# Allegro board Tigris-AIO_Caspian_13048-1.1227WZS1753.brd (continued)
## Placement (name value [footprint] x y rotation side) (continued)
R299  243R2F-2-GP  [R402H16]  45.59 85.7 90 top
R300  -  [0R0402-PAD]  155.88 84.85 270 top
R302  5K11R2F-L1-GP  [R402H16]  78.74 71.87 180 bottom
R303  8K45R2F-2-GP  [R402H16]  95.5 90.79 90 top
R304  1KR2F-3-GP  [R402H16]  79.76 71.87 180 bottom
R305  20KR2F-L-GP  [R402H16]  149.68 93.86 0 top
R306  20KR2F-L-GP  [R402H16]  153.82 95.13 90 top
R307  1KR2J-1-GP  [R402H16]  152.14 84.6 90 top
R308  2K1R2F-GP  [R402H16]  43.97 84.14 0 top
R309  2K1R2F-GP  [R402H16]  46 84.14 180 top
R311  0R5J-5-GP  [R805H24]  13.23 83.91 270 top
R312  10MR3F-GP  [R603H22]  155.42 86.78 0 top
R313  10KR2J-3-GP  [R402H16]  152.15 83.55 90 top
R314  4K7R2J-2-GP  [R402H16]  154.91 90.28 0 top
R316  7K5R2F-1DL-GP  [R402H16]  122.01 83.16 0 top
R318  1KR2J-1-GP  [R402H16]  125.25 101.05 0 bottom
R320  243R2F-2-GP  [R402H16]  45.59 82.52 90 top
R321  1KR2J-1-GP  [R402H16]  152.15 82.41 270 top
R322  1KR2J-1-GP  [R402H16]  125.45 98.46 0 bottom
R323  2K2R2J-2-GP  [R402H16]  177.04 82.41 270 top
R324  2K2R2J-2-GP  [R402H16]  179.07 82.41 270 top
R325  0R5J-5-GP  [R805H24]  37.8 82.33 270 top
R329  47KR2F-GP  [R402H16]  112.39 81.64 270 top
R331  10KR2F-2-GP  [R402H16]  181.61 81.9 180 top
R332  5K1R2F-2-GP  [R402H16]  182.88 81.9 180 top
R333  20KR2F-L-GP  [R402H16]  184.15 81.9 0 top
R334  1KR2J-1-GP  [R402H16]  157.48 81.81 270 top
R335  1KR2J-1-GP  [R402H16]  149.61 81.26 90 top
R336  2K2R2J-2-GP  [R402H16]  177.04 81.26 270 top
R337  10KR2J-3-GP  [R402H16]  179.07 81.26 90 top
R340  10KR2J-3-GP  [R402H16]  120.4 80.88 270 top
R341  40D2R2F-GP  [R402H16]  45.59 80.75 270 top
R342  1KR2J-1-GP  [R402H16]  151.51 80.66 180 top
R343  1KR2J-1-GP  [R402H16]  152.52 80.66 180 top
R344  0R5J-5-GP  [R805H24]  37.8 80.4 270 top
R345  47KR2F-GP  [R402H16]  110.74 80.37 0 top
R346  10KR2J-3-GP  [R402H16]  155.45 80.46 270 top
R347  33R2J-2-GP  [R402H16]  159.1 80.16 270 top
R348  10KR2J-3-GP  [R402H16]  33.32 80.1 90 top
R349  10KR2J-3-GP  [R402H16]  120.4 79.74 270 top
R350  10KR2J-3-GP  [R402H16]  162.94 79.1 90 top
R351  10R2F-L-GP  [R402H14]  177.42 79.61 180 top
R352  40D2R2F-GP  [R402H16]  45.59 79.6 270 top
R353  33R2J-2-GP  [R402H16]  159.1 79.11 270 top
R354  0R2J-2-GP  [R402H16]  108.71 78.85 90 top
R355  10KR2J-3-GP  [R402H16]  162.94 77.96 90 top
R356  1KR2J-1-GP  [R402H16]  110.74 78.34 0 top
R357  10KR2J-3-GP  [R402H16]  159.1 78.07 90 top
R358  -  [0R0805-PAD]  31.8 77.78 0 top
R359  2D2R5J-1-GP  [R805H24]  33.76 77.78 0 top
R360  0R0402-PAD-2-GP  [0R0402-PAD-1]  108.71 77.71 270 top
R361  10KR2J-3-GP  [R402H16]  153.16 77.45 270 top
R362  7K15R2F-L-GP  [R402H16]  30.28 77.17 180 top
R366  33R2J-2-GP  [R402H16]  159.1 77.03 270 top
R367  10KR2J-3-GP  [R402H16]  162.94 76.27 90 top
R368  0R0603-PAD-2-GP-U  [0R0603-PAD-1-U]  190.17 77.17 0 bottom
R371  2D2R3J-2-GP  [R603H22]  37.29 76.72 90 top
R372  33R2J-2-GP  [R402H16]  159.1 75.99 270 top
R373  10KR2J-3-GP  [R402H16]  162.94 75.23 90 top
R374  10KR2J-3-GP  [R402H16]  155.45 75.68 270 top
R375  -  [0R0402-PAD]  192.66 74.3 180 top
R377  33R2J-2-GP  [R402H16]  159.1 74.95 270 top
R378  10KR2J-3-GP  [R402H16]  162.94 74.19 90 top
R379  33R2J-2-GP  [R402H16]  155.45 74.53 270 top
R380  100KR2F-L1-GP  [R402H16]  193.17 72.81 90 top
R381  1KR2J-1-GP  [R402H16]  162.93 73.11 270 top
R382  7K5R2F-1DL-GP  [R402H16]  119.51 73.64 0 top
R383  1KR2J-1-GP  [R402H16]  155.45 73.39 270 top
R384  10KR2J-3-GP  [R402H16]  38.61 72.88 270 top
R385  10KR2J-3-GP  [R402H16]  159.13 72.75 270 top
R386  1MR3F-GP  [R603H22]  198.63 73.52 0 top
R387  0R0402-PAD-2-GP  [0R0402-PAD-1]  162.94 71.99 270 top
R388  8K45R2F-2-GP  [R402H16]  92.48 90 270 bottom
R389  33R2J-2-GP  [R402H16]  155.44 72.31 270 top
R391  2K2R2J-2-GP  [R402H16]  114.3 81.64 90 top
R392  33R2J-2-GP  [R402H16]  155.44 71.27 270 top
R394  2KR2F-3-GP  [R402H16]  90.07 89.62 180 bottom
R395  33R2J-2-GP  [R402H16]  159.13 70.5 270 top
R396  10KR2J-L-GP  [R402H15]  76.45 71.1 180 bottom
R397  10KR2J-L-GP  [R402H15]  77.62 71.08 180 bottom
R398  10KR2J-L-GP  [R402H15]  76.45 71.1 0 top
R399  10KR2J-L-GP  [R402H15]  75.31 71.87 0 top
R400  158R2F-GP  [R402H16]  38.61 69.96 90 top
R403  100R2F-L1-GP-U  [R402H14]  87.37 69.82 0 top
R406  0R3J-0-U-GP  [R603H22]  26.34 69.38 270 top
R407  1KR2J-1-GP  [R402H16]  159.13 69.36 270 top
R408  22D6R2F-L1-GP  [R402H16]  153.54 69.33 0 top
R410  2K21R3F-L-GP  [R603H22]  38.48 68.82 270 top
R411  7K5R2F-1DL-GP  [R402H16]  120.65 68.73 0 top
R412  158R2F-GP  [R402H16]  36.2 68.69 90 top
R413  100KR2J-1-GP  [R402H16]  82.75 68.54 0 top
R415  1KR2J-1-GP  [R402H16]  159.13 68.22 270 top
R417  3K3R2F-2-GP  [R402H16]  32.29 67.82 0 top
R418  2K21R3F-L-GP  [R603H22]  36.96 67.55 90 top
R419  1KR2J-1-GP  [R402H16]  153.54 67.33 0 top
R420  75R2F-2-GP  [R402H16]  38.86 67.17 0 top
R421  0R0402-PAD-2-GP  [0R0402-PAD-1]  159.13 67.07 270 top
R422  47KR2F-GP  [R402H16]  51.69 66.91 0 top
R423  100KR2J-1-GP  [R402H16]  52.83 66.91 180 top
R424  1KR2J-1-GP  [R402H16]  148.08 32.75 90 top
R425  1KR2J-1-GP  [R402H16]  141.48 32.62 0 top
R426  10KR2J-3-GP  [R402H16]  55.17 66.45 90 top
R427  10KR2J-3-GP  [R402H16]  111.85 65.34 270 top
R428  100KR2J-1-GP  [R402H16]  51.49 64.79 0 top
R429  0R0402-PAD-2-GP  [0R0402-PAD-1]  161.87 63.96 0 top
R430  4K7R2J-2-GP  [R402H16]  33.78 64.63 180 top
R431  0R5J-5-GP  [R805H24]  36.17 63.79 270 top
R432  10KR2J-3-GP  [R402H16]  149.86 61.71 0 top
R433  100KR2J-1-GP  [R402H16]  51.49 62.89 0 top
R434  22R2J-2-GP  [R402H16]  154.58 59.04 180 top
R435  33R2J-2-GP  [R402H16]  161.87 61.8 0 top
R436  33R2J-2-GP  [R402H16]  163.01 61.8 0 top
R437  10KR2F-2-GP  [R402H16]  86.87 61.71 270 top
R438  0R0402-PAD-2-GP  [0R0402-PAD-1]  156.46 61.71 180 top
R439  22R2J-2-GP  [R402H16]  151.38 59.04 0 top
R440  1KR2J-1-GP  [R402H16]  46.05 60.77 180 top
R441  1KR2J-1-GP  [R402H16]  41.33 59.93 0 top
R442  150R2F-1-GP  [R402H16]  137.41 59.4 0 top
R443  150R2F-1-GP  [R402H16]  138.45 59.4 0 top
R444  150R2F-1-GP  [R402H16]  139.49 59.4 0 top
R445  10KR2J-3-GP  [R402H16]  46.38 59.04 270 top
R446  22R2J-2-GP  [R402H16]  152.5 59.04 180 top
R447  22R2J-2-GP  [R402H16]  153.51 59.04 180 top
R448  1KR2J-1-GP  [R402H16]  46.41 58 90 top
R449  0R0402-PAD-2-GP  [0R0402-PAD-1]  41.33 57.9 0 top
R450  10KR2J-3-GP  [R402H16]  58.88 55.97 180 top
R451  0R0402-PAD-2-GP  [0R0402-PAD-1]  60.05 55.91 0 top
R452  330KR2F-L-GP  [R402H16]  61.19 55.91 180 top
R453  -  [0R0402-PAD]  43.52 55.89 0 top
R454  33R2J-2-GP  [R402H16]  45.43 55.89 0 top
R455  10KR2J-3-GP  [R402H16]  46.62 55.88 180 top
R456  0R0402-PAD-2-GP  [0R0402-PAD-1]  42.42 55.86 0 top
R457  33R2J-2-GP  [R402H16]  50.67 55.86 0 top
R458  10KR2J-3-GP  [R402H16]  52.87 55.83 180 top
R459  33R2J-2-GP  [R402H16]  49.63 55.81 0 top
R460  10KR2J-3-GP  [R402H16]  51.82 55.81 0 top
R461  10KR2J-3-GP  [R402H16]  53.9 55.81 180 top
R462  -  [0R0805-PAD]  125.86 55.74 0 top
R463  10KR2J-3-GP  [R402H16]  48.13 55.46 270 top
R464  10KR2F-2-GP  [R402H16]  129.19 54.73 90 top
R465  0R2J-2-GP  [R402H16]  136.02 54.69 90 top
R466  20KR2J-L2-GP  [R402H16]  147.07 54.72 270 top
R467  1MR3F-GP  [R603H22]  118.41 54.17 90 top
R468  1KR2J-1-GP  [R402H16]  139.19 54.12 90 top
R469  10KR2J-3-GP  [R402H16]  145.16 54.72 90 top
R470  22KR2J-GP  [R402H16]  141.1 55.36 270 top
R471  10KR2J-3-GP  [R402H16]  149.35 45.07 0 top
R472  0R2J-2-GP  [R402H16]  148.34 45.07 0 top
R473  43R2J-GP  [R402H16]  65.02 53.32 270 top
R474  4K7R2J-2-GP  [R402H16]  150.88 43.29 180 top
R475  0R0402-PAD-2-GP  [0R0402-PAD-1]  142.62 46.08 270 top
R476  4K7R2J-2-GP  [R402H16]  139.83 44.18 90 top
R477  8K87R2F-2-GP  [R402H16]  128.11 53.19 270 top
R478  20KR2J-L2-GP  [R402H16]  42.09 53.17 90 top
R479  10KR2F-2-GP  [R402H16]  139.19 52.98 270 top
R480  4K7R2J-2-GP  [R402H16]  65.02 52.18 90 top
R481  0R0402-PAD-2-GP  [0R0402-PAD-1]  65.02 51.04 270 top
R482  4K7R2J-2-GP  [R402H16]  65.02 49.89 90 top
R483  4K7R2J-2-GP  [R402H16]  143.64 50.91 0 top
R484  1KR2J-1-GP  [R402H16]  144.53 49.39 90 top
R485  10KR2J-3-GP  [R402H16]  146.43 49.39 90 top
R486  0R0402-PAD-2-GP  [0R0402-PAD-1]  149.99 49.51 90 top
R487  20KR2J-L2-GP  [R402H16]  152.02 50.4 90 top
R488  0R0402-PAD-2-GP  [0R0402-PAD-1]  103.61 49.13 180 top
R489  20KR2J-L2-GP  [R402H16]  103.9 51.01 270 top
R490  8K2R2F-1-GP  [R402H16]  104.7 49.11 0 top
R491  4K7R2J-2-GP  [R402H16]  105.76 49.12 180 top
R492  4K7R2J-2-GP  [R402H16]  42.04 51.04 270 top
R493  4K7R2J-2-GP  [R402H16]  65.02 48.75 90 top
R494  1KR2J-1-GP  [R402H16]  38.35 48.24 270 top
R495  4K7R2J-2-GP  [R402H16]  42.04 49.77 270 top
R496  0R0402-PAD-2-GP  [0R0402-PAD-1]  65.02 47.61 270 top
R497  15KR2F-GP  [R402H16]  36.7 47.74 0 top
R498  8K2R2J-3-GP  [R402H16]  38.35 47.1 270 top
R499  0R3J-0-U-GP  [R603H22]  159.87 43.93 270 top
R500  2K2R2J-2-GP  [R402H16]  164.62 43.32 270 top
R501  4K7R2J-2-GP  [R402H16]  42.19 46.85 90 top
R503  10KR5F-2-GP  [R805H24]  6.86 46.21 270 top
R504  10KR2J-3-GP  [R402H16]  9.27 46.21 0 top
R505  4K7R2J-2-GP  [R402H16]  42.19 45.7 270 top
R506  0R3J-0-U-GP  [R603H22]  165.23 41.77 90 top
R507  3KR2J-2-GP  [R402H16]  17.73 45.58 90 top
R508  4K7R2J-2-GP  [R402H16]  125.13 45.2 270 top
R509  10KR2J-3-GP  [R402H16]  127.29 45.2 90 top
R511  0R3J-0-U-GP  [R603H22]  154.64 41.94 90 top
R512  -  [0R0805-PAD]  131.57 44.69 90 top
R513  4K7R2J-2-GP  [R402H16]  42.19 44.43 90 top
R514  20KR2F-L-GP  [R402H16]  104.78 44.43 90 top
R515  5K6R2F-2-GP  [R402H16]  160.78 40.5 180 top
R516  100KR2J-1-GP  [R402H16]  161.93 40.5 0 top
R517  10KR2F-2-GP  [R402H16]  163.07 40.5 0 top
R518  0R2J-2-GP  [R402H16]  65.02 44.18 90 top
R519  0R2J-2-GP  [R402H16]  101.22 43.93 180 top
R520  100KR2J-1-GP  [R402H16]  152.53 39.99 180 top
R521  4K7R2J-2-GP  [R402H16]  42.19 43.29 270 top
R522  0R3J-0-U-GP  [R603H22]  30.53 42.78 180 top
R523  -  [0R0402-PAD]  99.95 42.99 180 top
R524  330R3J-L-GP  [R603H22]  23.9 42.78 180 top
R526  0R3J-0-U-GP  [R603H22]  165.2 38.03 90 top
R527  10KR2J-3-GP  [R402H16]  41.81 40.9 90 top
R528  100KR2J-1-GP  [R402H16]  106.93 40.75 270 top
R529  10KR2J-3-GP  [R402H16]  108.84 40.75 270 top
R530  47KR2F-GP  [R402H16]  110.87 40.75 270 top
R531  100KR2J-1-GP  [R402H16]  112.83 40.73 90 top
R533  100R2F-L1-GP-U  [R402H14]  116.55 39.98 180 top
R534  2K2R2J-2-GP  [R402H16]  117.7 39.98 180 top
R535  10KR2J-3-GP  [R402H16]  42.01 39.58 270 top
R536  1KR2J-1-GP  [R402H16]  114.47 39.48 0 top
R537  10KR2J-3-GP  [R402H16]  16.76 39.23 90 top
R538  10R3J-3-GP  [R603H22]  154.05 34.65 180 top
R539  147KR2F-GP  [R402H16]  100.58 38.34 90 top
R540  3KR2J-2-GP  [R402H16]  16.76 38.08 270 top
R541  0R0402-PAD-2-GP  [0R0402-PAD-1]  164.72 33.77 180 top
R542  100KR2J-1-GP  [R402H16]  114.43 37.51 0 top
R543  10KR2J-3-GP  [R402H16]  41.91 37.32 90 top
R544  1KR2J-1-GP  [R402H16]  35.76 37.22 90 top
R545  10KR2J-3-GP  [R402H16]  40.39 36.56 180 top
R546  1MR3F-GP  [R603H22]  23.11 36.86 180 top
R547  10KR2J-3-GP  [R402H16]  41.91 36.18 90 top
R548  2KR2F-3-GP  [R402H16]  35.76 36.15 90 top
R549  33R2J-2-GP  [R402H16]  16.74 35.95 90 top
R550  200KR2F-L-GP  [R402H16]  102.47 35.35 180 top
R551  0R2J-2-GP  [R402H16]  43.69 36.69 0 top
R552  100KR2J-1-GP  [R402H16]  135.61 34.49 90 top
R553  100KR2J-1-GP  [R402H16]  137.57 34.45 90 top
R554  15KR2F-GP  [R402H16]  116.51 34.32 270 top
R555  2K49R2F-GP  [R402H16]  24.13 34.27 180 top
R556  10KR2J-3-GP  [R402H16]  118.24 33.89 180 top
R557  1KR2J-1-GP  [R402H16]  113.87 33.84 180 top
R558  1KR2J-1-GP  [R402H16]  114.91 33.84 180 top
R559  0R2J-2-GP  [R402H16]  35.76 33.08 90 top
R560  1KR2J-1-GP  [R402H16]  61.47 32.62 180 top
R561  10KR2J-3-GP  [R402H16]  62.48 32.62 0 top
R562  0R2J-2-GP  [R402H16]  60.32 32.58 180 top
R563  0R0402-PAD-2-GP  [0R0402-PAD-1]  58.14 32.55 0 top
R564  0R2J-2-GP  [R402H16]  59.16 32.55 0 top
R565  30KR2F-GP  [R402H16]  52.12 32.5 180 top
R566  30KR2F-GP  [R402H16]  53.19 32.5 180 top
R567  30KR2F-GP  [R402H16]  54.2 32.5 180 top
R568  160R2F-GP  [R402H16]  47.5 32.22 0 top
R569  4K7R2J-2-GP  [R402H16]  16.76 32.11 270 top
R571  33R2J-2-GP  [R402H16]  16.76 31.1 270 top
R572  0R0402-PAD-2-GP  [0R0402-PAD-1]  43.69 30.97 0 top
R573  4K7R2J-2-GP  [R402H16]  42.52 30.95 0 top
R574  30KR2F-GP  [R402H16]  47.5 30.31 180 top
R575  4K7R2J-2-GP  [R402H16]  112.04 30.08 0 top
R576  47KR2F-GP  [R402H16]  132.18 29.88 180 top
R577  10KR2J-3-GP  [R402H16]  133.48 29.88 180 top
R578  0R2J-2-GP  [R402H16]  160.53 22.08 0 top
R579  10KR2J-3-GP  [R402H16]  10.16 18.53 180 top
R583  2K2R2J-2-GP  [R402H16]  65.28 28.3 0 top
R584  47KR2F-GP  [R402H16]  132.08 28.15 270 top
R586  3D3R3F-GP  [R603H22]  147.57 21.07 0 top
R587  3D3R3F-GP  [R603H22]  147.57 23.99 180 top
R588  3D3R3F-GP  [R603H22]  147.57 26.91 0 top
R589  3D3R3F-GP  [R603H22]  147.57 29.83 180 top
R590  0R2J-2-GP  [R402H16]  159.51 22.08 0 top
R591  15KR2F-GP  [R402H16]  104.01 27.14 0 top
R592  10KR2J-3-GP  [R402H16]  105.16 27.14 180 top
R593  10KR2J-3-GP  [R402H16]  132.08 27.03 270 top
R595  330R3J-L-GP  [R603H22]  19.68 25.99 0 top
R596  330R3J-L-GP  [R603H22]  20.88 25.99 0 top
R597  100KR2J-1-GP  [R402H16]  139.19 32.62 0 top
R599  2K2R2J-2-GP  [R402H16]  59.31 24.75 180 top
R600  1MR2J-1-GP  [R402H16]  65.28 25.89 0 top
R601  100KR2J-1-GP  [R402H16]  134.08 24.64 0 top
R602  0R3J-0-U-GP  [R603H22]  14.48 24.85 90 bottom
R605  150R2F-1-GP  [R402H16]  32.44 21.93 0 top
R606  150R2F-1-GP  [R402H16]  39.09 21.88 0 top
R609  150R2F-1-GP  [R402H16]  37.9 22.18 0 top
R614  20KR2J-L2-GP  [R402H16]  62.91 20.18 270 top
R623  2K2R2J-2-GP  [R402H16]  33.1 11.72 90 top
R624  47R2J-2-GP  [R402H16]  70.38 7.82 180 top
R625  47R2J-2-GP  [R402H16]  71.52 7.82 180 top
R626  2K2R2J-2-GP  [R402H16]  32.54 6.87 270 top
R629  110R2F-GP  [R402H16]  19.3 245.96 0 bottom
R630  0R0402-PAD-2-GP  [0R0402-PAD-1]  17.07 245.96 180 bottom
R631  2D2R5J-1-GP  [R805H24]  14.73 245.91 90 bottom
R632  10KR2F-2-GP  [R402H16]  4.62 244.76 180 bottom
R633  1KR2J-1-GP  [R402H16]  11.07 245.5 180 bottom
R634  0R0402-PAD-2-GP  [0R0402-PAD-1]  9.91 245.53 0 bottom
R635  56K2R2F-2-GP  [R402H16]  25.2 245.25 90 bottom
R636  0R0402-PAD-2-GP  [0R0402-PAD-1]  58.42 245.22 180 bottom
R637  0R0402-PAD-2-GP  [0R0402-PAD-1]  57.28 245.22 180 bottom
R638  1KR2J-1-GP  [R402H16]  56.01 245.22 180 bottom
R639  51R2F-2-GP  [R402H16]  53.72 245.22 180 bottom
R640  825R2F-GP  [R402H16]  52.45 245.22 0 bottom
R641  100R2F-L1-GP-U  [R402H14]  51.31 245.22 0 bottom
R642  249R2F-GP  [R402H16]  50.04 245.22 180 bottom
R643  51R2J-2-GP  [R402H16]  48.77 245.22 180 bottom
R644  51R2J-2-GP  [R402H16]  47.5 245.22 180 bottom
R645  51R2J-2-GP  [R402H16]  46.23 245.22 180 bottom
R646  1KR2J-1-GP  [R402H16]  44.96 245.22 0 bottom
R647  1KR2J-1-GP  [R402H16]  22.38 244.48 180 bottom
R648  54D9R2F-L1-GP  [R402H16]  20.35 244.05 180 bottom
R649  90D9R2F-1-GP  [R402H16]  19.3 244.05 180 bottom
R650  0R0402-PAD-2-GP  [0R0402-PAD-1]  25.2 244.1 270 bottom
R651  0R0402-PAD-2-GP  [0R0402-PAD-1]  11.58 243.82 270 bottom
R652  100R2F-L1-GP-U  [R402H14]  9.68 243.82 90 bottom
R653  100R2F-L1-GP-U  [R402H14]  9.42 242.58 90 bottom
R654  100KR2J-1-GP  [R402H16]  105.16 242.55 180 bottom
R655  20K5R2F-GP  [R402H16]  22.89 242.45 270 bottom
R656  1K2R2F-1-GP  [R402H16]  11.56 241.54 90 bottom
R657  69K8R2F-GP  [R402H16]  22.89 241.31 270 bottom
R658  10KR2F-2-GP  [R402H16]  5.36 240.22 90 bottom
R659  0R0402-PAD-2-GP  [0R0402-PAD-1]  111.76 233.92 180 bottom
R660  100KR2J-1-GP  [R402H16]  105.16 240.52 0 bottom
R661  47D5R2F-1-GP  [R402H16]  11.58 240.29 270 bottom
R662  59KR2F-GP  [R402H16]  22.89 240.17 270 bottom
R663  10KR2F-2-GP  [R402H16]  4.93 238.74 0 bottom
R664  0R0402-PAD-2-GP  [0R0402-PAD-1]  112.78 233.92 180 bottom
R665  1KR2F-3-GP  [R402H16]  11.58 239.15 270 bottom
R666  68KR2F-GP  [R402H16]  22.89 239.02 270 bottom
R667  10KR2F-2-GP  [R402H16]  5.97 238.72 180 bottom
R668  560KR2F-GP  [R402H16]  8.92 238.52 0 bottom
R669  0R0402-PAD-2-GP  [0R0402-PAD-1]  114.68 234.68 270 bottom
R670  4K99R2F-L-GP  [R402H16]  10.95 237.63 0 bottom
R671  6K8R2F-2-GP  [R402H16]  24.92 237.12 270 bottom
R672  0R0402-PAD-2-GP  [0R0402-PAD-1]  114.68 235.7 270 bottom
R673  0R0402-PAD-2-GP  [0R0402-PAD-1]  9.4 236.8 270 bottom
R674  100KR2F-L1-GP  [R402H16]  22.38 236.61 0 bottom
R675  18KR2F-GP  [R402H16]  14.45 236.15 180 bottom
R676  0R0402-PAD-2-GP  [0R0402-PAD-1]  114.17 231.94 90 bottom
R677  1KR2J-1-GP  [R402H16]  10.95 235.47 0 bottom
R678  100KR2F-L1-GP  [R402H16]  21.87 235.09 270 bottom
R679  100KR2F-L1-GP  [R402H16]  19.84 235.09 270 bottom
R680  0R0402-PAD-2-GP  [0R0402-PAD-1]  108.2 221.6 180 bottom
R681  10R2F-L-GP  [R402H14]  18.29 234.68 0 bottom
R682  10R2F-L-GP  [R402H14]  23.5 234.55 180 bottom
R683  75KR2F-GP  [R402H16]  14.5 234.2 180 bottom
R684  10R2F-L-GP  [R402H14]  26.16 234.04 90 bottom
R685  0R0402-PAD-2-GP  [0R0402-PAD-1]  109.22 221.6 180 bottom
R686  174KR2F-GP  [R402H16]  16 233.66 90 bottom
R687  118KR3F-GP  [R603H22]  15.57 232.44 90 bottom
R688  31K6R2F-GP  [R402H16]  12.06 232.39 180 bottom
R689  10KR2F-2-GP  [R402H16]  9.78 232.39 180 bottom
R690  6K8R2F-2-GP  [R402H16]  22.38 232.17 180 bottom
R691  6K8R2F-2-GP  [R402H16]  20.35 232.17 180 bottom
R692  118KR3F-GP  [R603H22]  23.55 230.77 180 bottom
R693  118KR3F-GP  [R603H22]  20.29 229.73 180 bottom
R694  2D2R5J-1-GP  [R805H24]  14.54 229.29 270 bottom
R695  1KR2F-3-GP  [R402H16]  54.41 228.28 180 bottom
R696  1KR2J-1-GP  [R402H16]  53.39 228.28 0 bottom
R697  0R0402-PAD-2-GP  [0R0402-PAD-1]  52.25 228.28 0 bottom
R698  0R0402-PAD-2-GP  [0R0402-PAD-1]  51.1 228.28 0 bottom
R699  51R2J-2-GP  [R402H16]  49.07 228.28 0 bottom
R700  100KR2J-1-GP  [R402H16]  111.63 223.12 0 bottom
R701  51R2J-2-GP  [R402H16]  15.17 226.36 270 bottom
R702  100KR2J-1-GP  [R402H16]  112.01 221.6 90 bottom
R703  0R3J-0-U-GP  [R603H22]  167.39 223.25 270 bottom
R704  2D2R5J-1-GP  [R805H24]  19.11 222.93 270 bottom
R705  0R3J-0-U-GP  [R603H22]  169.42 222.49 0 bottom
R706  330R3J-L-GP  [R603H22]  116.71 223.38 180 bottom
R707  47KR2F-GP  [R402H16]  112.9 220.58 270 bottom
R708  100KR2J-1-GP  [R402H16]  112.9 219.44 90 bottom
R709  0R6J-3-GP  [R1206H28]  121.41 217.92 270 bottom
R710  -  [0R0805-PAD]  157.99 217.66 90 bottom
R711  -  [0R0805-PAD]  157.99 216.26 90 bottom
R712  -  [0R0805-PAD]  157.99 214.87 90 bottom
R713  100KR2J-1-GP  [R402H16]  126.64 213.6 0 bottom
R714  0R2J-2-GP  [R402H16]  125.6 213.6 0 bottom
R715  0R0402-PAD-2-GP  [0R0402-PAD-1]  124.59 213.6 0 bottom
R717  0R2J-2-GP  [R402H16]  122.56 213.6 180 bottom
R718  1KR2J-1-GP  [R402H16]  81.41 208.52 180 bottom
R719  1KR2J-1-GP  [R402H16]  79.63 208.52 180 bottom
R720  1KR2J-1-GP  [R402H16]  77.72 208.52 180 bottom
R721  1KR2J-1-GP  [R402H16]  76.2 208.52 180 bottom
R722  1KR2J-1-GP  [R402H16]  73.91 208.52 180 bottom
R723  1KR2J-1-GP  [R402H16]  72.01 208.52 180 bottom
R724  4K7R2J-2-GP  [R402H16]  121.41 208.39 180 bottom
R725  4K7R2J-2-GP  [R402H16]  120.4 208.39 180 bottom
R726  4K7R2J-2-GP  [R402H16]  118.87 208.16 270 bottom
R727  4K7R2J-2-GP  [R402H16]  116.97 208.16 90 bottom
R728  49D9R2F-GP  [R402H16]  66.55 207.5 0 bottom
R729  2D2R5J-1-GP  [R805H24]  14.41 206.93 270 bottom
R730  0R0402-PAD-2-GP  [0R0402-PAD-1]  137.92 205.72 90 bottom
R731  1KR2J-1-GP  [R402H16]  81.41 205.72 0 bottom
R732  1KR2J-1-GP  [R402H16]  79.63 205.72 0 bottom
R733  1KR2J-1-GP  [R402H16]  77.72 205.72 0 bottom
R734  1KR2J-1-GP  [R402H16]  76.33 205.72 0 bottom
R735  1KR2J-1-GP  [R402H16]  73.91 205.72 0 bottom
R736  1KR2J-1-GP  [R402H16]  72.01 205.72 0 bottom
R738  10KR2J-3-GP  [R402H16]  135.46 205.29 0 bottom
R739  1KR2J-1-GP  [R402H16]  134.37 203.44 180 bottom
R740  0R0402-PAD-2-GP  [0R0402-PAD-1]  85.45 205.26 0 bottom
R741  0R0402-PAD-2-GP  [0R0402-PAD-1]  84.3 205.26 0 bottom
R742  0R0402-PAD-2-GP  [0R0402-PAD-1]  60.58 205.09 270 bottom
R743  0R0402-PAD-2-GP  [0R0402-PAD-1]  67.69 204.45 180 bottom
R744  0R0402-PAD-2-GP  [0R0402-PAD-1]  66.55 204.45 0 bottom
R745  0R0402-PAD-2-GP  [0R0402-PAD-1]  63.37 204.33 180 bottom
R746  44D2R2F-GP  [R402H16]  62.21 204.32 180 bottom
R748  100KR2J-1-GP  [R402H16]  137.54 204.2 180 bottom
R749  75R2F-2-GP  [R402H16]  60.58 203.95 270 bottom
R750  51R2J-2-GP  [R402H16]  15.11 203.95 270 bottom
R751  1KR2J-1-GP  [R402H16]  81.41 203.69 180 bottom
R752  1KR2J-1-GP  [R402H16]  79.63 203.69 180 bottom
R753  1KR2J-1-GP  [R402H16]  77.72 203.69 180 bottom
R754  1KR2J-1-GP  [R402H16]  74.3 203.69 180 bottom
R755  1KR2J-1-GP  [R402H16]  72.39 203.69 180 bottom
R756  1KR2J-1-GP  [R402H16]  69.98 203.31 180 bottom
R757  1K8R2F-GP  [R402H16]  86.74 203.18 90 bottom
R758  24D9R2F-L-GP  [R402H16]  84.71 203.18 270 bottom
R759  1MR2J-L2-GP  [R402H16]  133.86 201.91 90 bottom
R760  100KR2J-1-GP  [R402H16]  131.95 201.91 90 bottom
R762  100KR2J-1-GP  [R402H16]  133.86 200.9 90 bottom
R763  1MR2J-L2-GP  [R402H16]  131.95 200.9 90 bottom
R764  0R0402-PAD-2-GP  [0R0402-PAD-1]  86.22 201.59 180 bottom
R765  3K3R2J-3-GP  [R402H16]  85.07 201.59 180 bottom
R767  90D9R2F-1-GP  [R402H16]  63.37 201.53 0 bottom
R768  100R2F-L1-GP-U  [R402H14]  62.23 201.48 180 bottom
R769  110R2F-GP  [R402H16]  61.09 201.48 180 bottom
R770  0R0402-PAD-2-GP  [0R0402-PAD-1]  59.95 201.48 180 bottom
R771  0R0402-PAD-2-GP  [0R0402-PAD-1]  69.98 201.41 0 bottom
R772  0R2J-2-GP  [R402H16]  68.83 201.41 180 bottom
R773  0R2J-2-GP  [R402H16]  67.79 201.41 0 bottom
R774  51R2J-2-GP  [R402H16]  66.78 201.41 0 bottom
R775  1KR2J-1-GP  [R402H16]  81.41 201.15 0 bottom
R776  1KR2J-1-GP  [R402H16]  74.3 201.15 0 bottom
R777  1KR2J-1-GP  [R402H16]  72.39 201.08 0 bottom
R779  2D2R5J-1-GP  [R805H24]  19.18 200.26 270 bottom
R783  -  [0R0805-PAD]  159 195.31 180 bottom
R784  -  [0R0805-PAD]  157.61 195.31 180 bottom
R785  -  [0R0805-PAD]  156.21 195.31 180 bottom
R786  -  [0R0805-PAD]  154.81 195.31 180 bottom
R787  -  [0R0805-PAD]  153.42 195.31 180 bottom
R788  -  [0R0805-PAD]  152.02 195.31 180 bottom
R789  -  [0R0805-PAD]  150.62 195.31 180 bottom
R790  -  [0R0805-PAD]  149.22 195.31 180 bottom
R791  2D2R5J-1-GP  [R805H24]  184.02 191.25 0 bottom
R792  2R2F-GP  [R402H16]  158.88 188.83 90 bottom
R793  2R2F-GP  [R402H16]  164.34 188.71 90 bottom
R794  10KR2F-2-GP  [R402H16]  179.83 188.58 0 bottom
R795  24D9R2F-L-GP  [R402H16]  165.86 188.32 180 bottom
R796  24D9R2F-L-GP  [R402H16]  160.53 187.31 0 bottom
R797  0R0402-PAD-2-GP  [0R0402-PAD-1]  158.5 187.31 0 bottom
R798  0R3J-0-U-GP  [R603H22]  13.89 187.4 90 bottom
R799  0R0402-PAD-2-GP  [0R0402-PAD-1]  163.45 186.04 0 bottom
R800  1KR2F-3-GP  [R402H16]  157.99 185.78 90 bottom
R801  1KR2F-3-GP  [R402H16]  159.51 185.28 0 bottom
R802  1KR2F-3-GP  [R402H16]  163.07 184.51 270 bottom
R803  1KR2F-3-GP  [R402H16]  162.43 182.99 0 bottom
R804  8K2R2F-1-GP  [R402H16]  14.3 184.24 270 bottom
R805  20KR2J-L2-GP  [R402H16]  12.27 184.24 90 bottom
R806  4K7R2J-2-GP  [R402H16]  10.79 184.64 180 bottom
R807  0R0402-PAD-2-GP  [0R0402-PAD-1]  14.22 183.12 270 bottom
R808  0R0402-PAD-2-GP  [0R0402-PAD-1]  173.48 180.2 270 bottom
R809  0R0402-PAD-2-GP  [0R0402-PAD-1]  158.75 179.92 90 bottom
R810  100R2F-L1-GP-U  [R402H14]  13.97 181.59 0 bottom
R811  2K2R2J-2-GP  [R402H16]  8.28 182.56 0 bottom
R812  10KR2J-3-GP  [R402H16]  24.9 176.72 90 bottom
R813  0R0805-PAD-2-GP-U  [0R0805-PAD-1-U]  24.46 174.3 0 bottom
R814  0R5J-5-GP  [R805H24]  16.18 158.28 0 bottom
R815  0R5J-5-GP  [R805H24]  14.15 158.28 0 bottom
R816  0R5J-5-GP  [R805H24]  18.21 158.28 0 bottom
R817  100KR2J-1-GP  [R402H16]  185.55 162.42 180 bottom
R818  10KR2J-3-GP  [R402H16]  184.53 162.42 180 bottom
R819  100KR2J-1-GP  [R402H16]  183.39 162.42 180 bottom
R820  100KR2J-1-GP  [R402H16]  181.84 163.31 0 bottom
R821  100KR2J-1-GP  [R402H16]  186.59 162.38 0 bottom
R822  56KR3F-GP  [R603H22]  17.02 148.47 0 bottom
R823  0R2J-2-GP  [R402H16]  79.78 158.47 270 bottom
R824  0R3J-0-U-GP  [R603H22]  82.07 158.22 90 bottom
R825  100KR2J-1-GP  [R402H16]  17.4 146.52 90 bottom
R826  0R2J-2-GP  [R402H16]  83.26 157.05 270 bottom
R827  191R2F-GP  [R402H16]  177.47 156.93 270 bottom
R828  49D9R2F-GP  [R402H16]  75.08 156.64 0 bottom
R829  49D9R2F-GP  [R402H16]  74.04 156.64 0 bottom
R830  24D9R2F-L-GP  [R402H16]  77.19 156.44 180 bottom
R831  24D9R2F-L-GP  [R402H16]  76.15 156.44 180 bottom
R832  0R3J-0-U-GP  [R603H22]  19.05 138.29 270 bottom
R833  0R0402-PAD-2-GP  [0R0402-PAD-1]  186.94 155.18 90 bottom
R834  0R3J-0-U-GP  [R603H22]  19.05 137.12 270 bottom
R835  22R2J-2-GP  [R402H16]  186.94 154.03 270 bottom
R836  0R3J-0-U-GP  [R603H22]  19.05 135.95 270 bottom
R837  22R2J-2-GP  [R402H16]  186.94 152.89 270 bottom
R838  0R0402-PAD-2-GP  [0R0402-PAD-1]  185.55 150.61 180 bottom
R839  22R2J-2-GP  [R402H16]  183.01 151.37 90 bottom
R840  22R2J-2-GP  [R402H16]  181.23 152 180 bottom
R841  22R2J-2-GP  [R402H16]  180.09 152 180 bottom
R842  0R3J-0-U-GP  [R603H22]  19.05 134.78 270 bottom
R843  0R5J-5-GP  [R805H24]  15.75 133.84 180 top
R844  0R5J-5-GP  [R805H24]  17.78 133.84 180 top
R845  0R0402-PAD-2-GP  [0R0402-PAD-1]  159.26 146.67 0 bottom
R846  1KR2F-3-GP  [R402H16]  161.54 146.64 180 bottom
R847  1KR2F-3-GP  [R402H16]  160.4 146.64 0 bottom
R848  10KR2J-3-GP  [R402H16]  163.83 127.49 90 bottom
R849  10KR2J-3-GP  [R402H16]  170 125.41 180 bottom
R850  10KR2J-3-GP  [R402H16]  150.6 124.8 0 bottom
R851  10KR2J-3-GP  [R402H16]  153.7 124.72 0 bottom
R852  10KR2J-3-GP  [R402H16]  163.83 124.57 90 bottom
R853  0R6J-3-GP  [R1206H28]  14.73 123.73 90 bottom
R854  -  [0R0805-PAD]  144.93 115.63 180 bottom
R855  15KR2F-GP  [R402H16]  183.97 115.5 180 bottom
R856  10KR2J-3-GP  [R402H16]  182.83 115.5 0 bottom
R857  1KR2F-3-GP  [R402H16]  136.14 114.54 270 bottom
R858  1KR2F-3-GP  [R402H16]  136.42 113.47 270 bottom
R859  1KR2J-1-GP  [R402H16]  185.78 107.81 270 bottom
R860  2D2R3J-2-GP  [R603H22]  129.67 106.82 180 bottom
R861  105KR2F-1-GP  [R402H16]  159.77 102.09 0 bottom
R862  0R0402-PAD-2-GP  [0R0402-PAD-1]  130.3 100.82 270 bottom
R863  10KR2J-3-GP  [R402H16]  141.97 99.42 90 bottom
R864  200R2F-L-GP  [R402H16]  132.28 99.36 180 bottom
R865  200R2F-L-GP  [R402H16]  131.21 99.36 180 bottom
R866  200R2F-L-GP  [R402H16]  130.07 99.36 180 bottom
R867  1KR2J-1-GP  [R402H16]  129.03 99.35 0 bottom
R868  10KR2J-3-GP  [R402H16]  127.99 99.35 0 bottom
R869  2K2R2J-2-GP  [R402H16]  126.97 99.35 180 bottom
R870  243R2F-2-GP  [R402H16]  45.72 98.65 270 bottom
R871  1KR2J-1-GP  [R402H16]  155.93 83.35 180 top
R872  1KR2J-1-GP  [R402H16]  157.45 82.84 270 top
R873  10KR2J-3-GP  [R402H16]  141.98 98.34 270 bottom
R877  1KR2J-1-GP  [R402H16]  141.55 96.77 180 bottom
R878  1KR2J-1-GP  [R402H16]  143.8 96.76 0 bottom
R879  0R0402-PAD-2-GP  [0R0402-PAD-1]  142.64 96.74 0 bottom
R880  10KR2J-3-GP  [R402H16]  148.59 96.63 0 bottom
R885  2K1R2F-GP  [R402H16]  46.35 96.24 180 bottom
R886  2K1R2F-GP  [R402H16]  45.21 96.24 0 bottom
R887  0R0402-PAD-2-GP  [0R0402-PAD-1]  134.82 96.23 180 bottom
R888  10KR2J-3-GP  [R402H16]  133.75 96.23 180 bottom
R889  100R2F-L1-GP-U  [R402H14]  131.95 96 180 bottom
R890  100R2F-L1-GP-U  [R402H14]  130.81 96 180 bottom
R891  100R2F-L1-GP-U  [R402H14]  129.67 96 180 bottom
R892  1KR2J-1-GP  [R402H16]  128.52 96 180 bottom
R893  1KR2J-1-GP  [R402H16]  124.96 95.78 90 bottom
R895  10KR2J-3-GP  [R402H16]  126.49 94.6 0 bottom
R896  33KR2J-3-GP  [R402H16]  184.25 95.51 180 bottom
R897  0R2J-2-GP  [R402H16]  178.31 95.36 0 bottom
R898  10KR2J-3-GP  [R402H16]  124.96 94.76 270 bottom
R899  243R2F-2-GP  [R402H16]  45.84 94.72 270 bottom
R902  0R0603-PAD-2-GP-U  [0R0603-PAD-1-U]  178.28 88.5 180 bottom
R903  1KR2J-1-GP  [R402H16]  131.95 94.09 0 bottom
R905  10KR2J-3-GP  [R402H16]  134.11 93.96 180 bottom
R906  15R2J-GP  [R402H16]  129.67 93.96 0 bottom
R908  10KR2J-3-GP  [R402H16]  144.47 93.85 0 bottom
R909  2K2R2J-2-GP  [R402H16]  146.69 93.84 0 bottom
R910  2K2R2J-2-GP  [R402H16]  145.54 93.84 0 bottom
R911  10KR2J-3-GP  [R402H16]  142.62 93.84 0 bottom
R912  0R0402-PAD-2-GP  [0R0402-PAD-1]  139.06 94.47 0 bottom
R913  1KR2J-1-GP  [R402H16]  124.96 93.74 270 bottom
R914  47KR2F-GP  [R402H16]  131.95 92.06 180 bottom
R915  1K5R2J-3-GP  [R402H16]  130.81 92.06 0 bottom
R916  1KR2J-1-GP  [R402H16]  129.67 92.06 0 bottom
R917  15R2J-GP  [R402H16]  127.76 92.06 0 bottom
R918  10KR2J-3-GP  [R402H16]  125.6 92.06 0 bottom
R919  10KR2J-3-GP  [R402H16]  123.95 92.06 0 bottom
R920  1KR2J-1-GP  [R402H16]  151.89 91.84 0 bottom
R921  2K2R2J-2-GP  [R402H16]  149.86 91.84 0 bottom
R922  10KR2J-3-GP  [R402H16]  148.79 91.84 0 bottom
R923  2K2R2J-2-GP  [R402H16]  147.75 91.84 0 bottom
R924  2K1R2F-GP  [R402H16]  62.23 92.68 90 bottom
R925  1KR2J-1-GP  [R402H16]  140.34 91.55 180 bottom
R926  1KR2J-1-GP  [R402H16]  140.21 94.47 180 bottom
R927  10KR2J-3-GP  [R402H16]  138.21 91.11 180 bottom
R928  2K1R2F-GP  [R402H16]  60.76 92.24 180 bottom
R933  2K2R2J-2-GP  [R402H16]  148.59 87.52 270 bottom
R935  4K42R2F-GP  [R402H16]  97.03 91.3 180 top
R936  1KR2J-1-GP  [R402H16]  155.08 89.77 270 bottom
R937  10KR2J-3-GP  [R402H16]  153.1 89.77 90 bottom
R938  10KR2J-3-GP  [R402H16]  128.77 86.76 0 bottom
R939  10KR2J-3-GP  [R402H16]  127.76 86.76 0 bottom
R940  2KR2F-3-GP  [R402H16]  99.49 91.37 0 top
R943  8K45R2F-2-GP  [R402H16]  92.48 91.14 270 bottom
R945  2K1R2F-GP  [R402H16]  45.97 84.17 0 bottom
R946  2K1R2F-GP  [R402H16]  43.94 84.17 180 bottom
R947  10KR2J-3-GP  [R402H16]  143.51 83.84 270 bottom
R948  2KR2F-3-GP  [R402H16]  90.07 91.53 0 bottom
R951  2K1R2F-GP  [R402H16]  45.59 82.7 270 bottom
R952  2D2R5J-1-GP  [R805H24]  32.28 82.31 90 bottom
R953  0R2J-2-GP  [R402H16]  149.75 82.04 90 bottom
R957  2K1R2F-GP  [R402H16]  45.46 80.75 90 bottom
R959  2K1R2F-GP  [R402H16]  46.1 79.09 180 bottom
R960  2K1R2F-GP  [R402H16]  44.96 79.09 0 bottom
R961  0R0603-PAD-2-GP-U  [0R0603-PAD-1-U]  192.79 93.96 0 top
R962  10KR2J-3-GP  [R402H16]  149.86 78.6 270 bottom
R963  10KR2J-L-GP  [R402H15]  77.62 71.08 0 top
R970  0R0603-PAD-2-GP  [0R0603-PAD-1]  138.15 76.22 0 bottom
R973  10KR2J-3-GP  [R402H16]  124.25 75.58 90 bottom
R977  10KR2J-3-GP  [R402H16]  124.25 74.54 90 bottom
R978  10KR2J-3-GP  [R402H16]  124.28 72.31 90 bottom
R979  2D2R5J-1-GP  [R805H24]  29.97 73.39 180 bottom
R980  10KR2J-3-GP  [R402H16]  124.28 73.34 90 bottom
R981  10KR2J-3-GP  [R402H16]  150.07 72.64 270 bottom
R982  7K5R2F-1DL-GP  [R402H16]  132.25 68.67 270 bottom
R984  10R2F-L-GP  [R402H14]  38.35 67.8 270 bottom
R985  2K2R2J-2-GP  [R402H16]  138.82 67.43 270 bottom
R986  10KR2J-3-GP  [R402H16]  150.07 71.63 270 bottom
R987  8K2R2F-1-GP  [R402H16]  128.01 65.93 0 bottom
R988  7K5R2F-1DL-GP  [R402H16]  130.52 65.51 270 bottom
R989  22R2J-2-GP  [R402H16]  141.3 65.25 0 bottom
R990  649R2F-GP  [R402H16]  140.15 65.25 180 bottom
R991  2K2R2J-2-GP  [R402H16]  143.23 66.16 90 bottom
R992  0R0603-PAD-2-GP-U  [0R0603-PAD-1-U]  137.39 63.36 0 bottom
R993  2K2R2J-2-GP  [R402H16]  143.61 62.07 90 bottom
R994  22R2J-2-GP  [R402H16]  146.94 62.01 90 bottom
R995  2K2R2J-2-GP  [R402H16]  143.61 61.02 90 bottom
R996  1R2F-GP  [R402H16]  139.11 60.06 90 bottom
R997  2K2R2J-2-GP  [R402H16]  144.63 59.85 90 bottom
R998  2K2R2J-2-GP  [R402H16]  144.63 58.78 90 bottom
R999  0R0805-PAD-2-GP-U  [0R0805-PAD-1-U]  135.5 54.76 180 bottom
R1000  -  [0R0805-PAD]  98.86 52.61 270 bottom
R1001  4K7R2J-2-GP  [R402H16]  62.43 51.95 0 bottom
R1002  -  [0R0805-PAD]  98.88 50.66 270 bottom
R1003  10KR2J-3-GP  [R402H16]  141.22 51.58 180 bottom
R1004  10KR2J-3-GP  [R402H16]  58.17 51.29 0 bottom
R1005  -  [0R0402-PAD]  98.81 49.26 90 bottom
R1008  2KR2F-3-GP  [R402H16]  56.08 48.78 180 bottom
R1009  33R2J-2-GP  [R402H16]  51.54 48.68 0 bottom
R1010  10KR2F-2-GP  [R402H16]  54.99 48.62 0 bottom
R1011  10KR2J-3-GP  [R402H16]  53.85 48.62 180 bottom
R1012  33R2J-2-GP  [R402H16]  52.7 48.62 0 bottom
R1013  -  [0R0805-PAD]  98.83 47.86 270 bottom
R1014  10KR2J-3-GP  [R402H16]  137.29 47.86 180 bottom
R1015  2K2R2J-2-GP  [R402H16]  131.7 47.86 270 bottom
R1017  22KR2F-GP  [R402H16]  58.17 48.75 0 bottom
R1018  10KR2J-3-GP  [R402H16]  131.7 46.82 270 bottom
R1019  0R0402-PAD-2-GP  [0R0402-PAD-1]  56.74 46.72 270 bottom
R1020  15KR2F-GP  [R402H16]  49.96 46.62 180 bottom
R1022  16KR2F-GP  [R402H16]  60.83 45.32 180 bottom
R1023  220R2F-GP  [R402H16]  50.01 44.64 0 bottom
R1024  0R0402-PAD-2-GP  [0R0402-PAD-1]  13.51 44.03 90 bottom
R1025  6K8R2F-2-GP  [R402H16]  61.29 43.77 270 bottom
R1026  47KR2F-GP  [R402H16]  55.14 43.77 180 bottom
R1027  121R3F-1-GP  [R603H22]  19.94 42.4 180 top
R1028  4K7R2J-2-GP  [R402H16]  13.51 42.96 90 bottom
R1029  10KR2F-2-GP  [R402H16]  43.59 42.88 0 bottom
R1030  8K2R2F-1-GP  [R402H16]  42.04 43.29 270 bottom
R1031  121R3F-1-GP  [R603H22]  21.18 44.71 180 top
R1032  0R0402-PAD-2-GP  [0R0402-PAD-1]  58.17 41.77 90 bottom
R1033  0R2J-2-GP  [R402H16]  19.2 41.69 180 bottom
R1034  33R2J-2-GP  [R402H16]  58.55 40.24 0 bottom
R1035  0R3J-0-U-GP  [R603H22]  50.98 41.59 0 bottom
R1036  0R2J-2-GP  [R402H16]  13.08 41.39 180 bottom
R1037  30KR2F-GP  [R402H16]  41.83 41.34 270 bottom
R1038  68KR2F-GP  [R402H16]  48.84 41.28 180 bottom
R1039  22KR2F-GP  [R402H16]  47.83 41.28 0 bottom
R1040  4K7R2J-2-GP  [R402H16]  20.4 40.8 0 bottom
R1041  16K5R2F-2-GP  [R402H16]  60.83 38.08 180 bottom
R1042  33KR2F-GP  [R402H16]  41.33 40.29 90 bottom
R1043  121R3F-1-GP  [R603H22]  17.27 40.5 270 top
R1044  0R0402-PAD-2-GP  [0R0402-PAD-1]  56.74 40.17 0 bottom
R1045  10KR2J-3-GP  [R402H16]  107.29 39.61 180 bottom
R1046  47KR2F-GP  [R402H16]  62.87 39.61 270 bottom
R1047  200KR2F-L-GP  [R402H16]  60.96 39.61 90 bottom
R1048  0R0402-PAD-2-GP  [0R0402-PAD-1]  112.56 39.35 180 bottom
R1049  2KR2F-3-GP  [R402H16]  41.88 39.18 270 bottom
R1050  121R3F-1-GP  [R603H22]  21.21 40.88 0 top
R1051  10KR2J-3-GP  [R402H16]  59.18 37.07 90 bottom
R1052  4K7R2J-2-GP  [R402H16]  52.96 38.69 90 bottom
R1053  22KR2J-GP  [R402H16]  49.83 38.41 180 bottom
R1054  -  [0R0603-PAD]  35.94 38.21 0 bottom
R1055  0R2J-2-GP  [R402H16]  105.92 39.61 0 bottom
R1056  10KR2J-3-GP  [R402H16]  107.34 37.68 180 bottom
R1057  8K2R2F-1-GP  [R402H16]  41.91 36.81 180 bottom
R1058  7K15R2F-L-GP  [R402H16]  40.79 36.64 0 bottom
R1059  8K2R2F-1-GP  [R402H16]  55.75 36.43 180 bottom
R1060  30KR2F-GP  [R402H16]  49.78 36.43 0 bottom
R1061  1KR2J-1-GP  [R402H16]  16.28 36.56 0 bottom
R1062  33R2J-2-GP  [R402H16]  15.14 36.56 180 bottom
R1063  -  [0R0402-PAD]  13.97 36.56 180 bottom
R1064  680R2F-GP  [R402H16]  54.69 36.41 0 bottom
R1065  0R5J-5-GP  [R805H24]  37.03 35.77 90 bottom
R1066  4K7R2J-2-GP  [R402H16]  117.47 35.54 90 bottom
R1067  0R2J-2-GP  [R402H16]  59.23 34.93 90 bottom
R1068  4K7R2J-2-GP  [R402H16]  44.45 34.78 90 bottom
R1069  10KR2J-3-GP  [R402H16]  41.5 34.58 90 bottom
R1070  10KR2J-3-GP  [R402H16]  34.67 34.4 180 bottom
R1071  10KR2J-3-GP  [R402H16]  42.98 34.17 180 bottom
R1072  10KR2J-3-GP  [R402H16]  44.5 33.69 270 bottom
R1073  10KR2J-3-GP  [R402H16]  41.5 33.56 90 bottom
R1074  1K5R3-GP  [R603H22]  118.85 41.82 180 top
R1075  7K15R2F-L-GP  [R402H16]  51.44 33.38 270 bottom
R1076  30KR2F-GP  [R402H16]  46.1 33.13 0 bottom
R1077  0R5J-5-GP  [R805H24]  119.66 33.03 0 bottom
R1078  4K7R2J-2-GP  [R402H16]  23.57 32.85 90 bottom
R1079  4K7R2J-2-GP  [R402H16]  130.48 32.7 0 bottom
R1080  10KR2J-3-GP  [R402H16]  61.34 35.7 270 bottom
R1081  100KR2J-1-GP  [R402H16]  52.35 31.91 0 bottom
R1082  8K2R2F-1-GP  [R402H16]  51.31 31.91 0 bottom
R1083  33R2J-2-GP  [R402H16]  23.57 31.66 90 bottom
R1087  1K5R3-GP  [R603H22]  123.09 30.01 270 bottom
R1088  -  [0R0805-PAD]  100.25 29.91 90 bottom
R1090  8K2R2J-3-GP  [R402H16]  25.53 29.45 0 bottom
R1091  470R2J-2-GP  [R402H16]  50.04 29.07 270 top
R1092  470R2J-2-GP  [R402H16]  38.23 29.32 180 top
R1093  -  [0R0805-PAD]  100.25 28.38 90 bottom
R1094  470R2J-2-GP  [R402H16]  50.04 27.8 270 top
R1096  8K2R2J-3-GP  [R402H16]  20.27 27.11 90 bottom
R1097  470R2J-2-GP  [R402H16]  38.23 27.42 0 top
R1100  -  [0R0805-PAD]  100.25 26.86 90 bottom
R1101  470R2J-2-GP  [R402H16]  50.04 26.78 270 top
R1103  470R2J-2-GP  [R402H16]  37.21 26.65 180 top
R1104  10KR2J-3-GP  [R402H16]  24.51 25.76 0 bottom
R1105  470R2J-2-GP  [R402H16]  50.04 25.51 270 top
R1107  39K2R2F-L-GP  [R402H16]  20.07 25.59 180 bottom
R1108  -  [0R0805-PAD]  100.25 25.33 90 bottom
R1109  470R2J-2-GP  [R402H16]  37.21 24.75 0 top
R1113  -  [0R0805-PAD]  100.25 23.81 90 bottom
R1114  100R2F-L1-GP-U  [R402H14]  32.61 21.98 180 bottom
R1115  2K2R2J-2-GP  [R402H16]  31.7 20.05 0 bottom
R1116  2K2R2J-2-GP  [R402H16]  33.44 16.4 90 bottom
R1117  100R2F-L1-GP-U  [R402H14]  32.94 14 0 bottom
R1118  -  [0R0805-PAD]  111.18 14.51 90 bottom
R1119  -  [0R0805-PAD]  111.18 12.48 90 bottom
R1120  1KR2F-3-GP  [R402H16]  129.11 218.42 180 top
R1121  1KR2J-1-GP  [R402H16]  189.36 92.59 270 top
R1122  1KR2J-1-GP  [R402H16]  189.1 91.55 90 top
R1123  0R3J-0-U-GP  [R603H22]  19.05 133.61 270 bottom
R1124  0R3J-0-U-GP  [R603H22]  19.05 132.44 270 bottom
R1125  0R3J-0-U-GP  [R603H22]  19.05 131.28 270 bottom
R1126  0R3J-0-U-GP  [R603H22]  19.05 144.13 270 bottom
R1133  47KR2F-GP  [R402H16]  33.78 156.7 0 top
R1135  10KR2J-3-GP  [R402H16]  33.02 155.05 270 top
R1136  150KR2J-GP  [R402H16]  32.38 159.88 270 top
R1137  47KR2J-2-GP  [R402H16]  30.48 159.88 270 top
R1138  100KR2J-1-GP  [R402H16]  33.91 158.61 180 top
R1139  22KR2J-GP  [R402H16]  38.1 154.67 90 top
R1141  10KR2F-2-GP  [R402H16]  19 144.71 180 top
R1142  10KR2F-2-GP  [R402H16]  23.98 145.73 270 top
R1143  49K9R2F-L-GP  [R402H16]  23.98 144.59 270 top
R1144  47KR2F-GP  [R402H16]  24 142.22 90 top
R1146  100KR2F-L1-GP  [R402H16]  31.8 153.96 90 top
R1147  0R0402-PAD-2-GP  [0R0402-PAD-1]  41.27 151.75 0 top
R1149  100KR2F-L1-GP  [R402H16]  33.83 153.96 90 top
R1150  0R3J-0-U-GP  [R603H22]  24.43 144.76 90 bottom
R1151  0R3J-0-U-GP  [R603H22]  27.51 147.66 180 top
R1152  D01R2512F-3-GP  [R2512H32]  24.56 147.56 270 bottom
R1153  10KR2J-3-GP  [R402H16]  121.46 98.64 0 top
R1154  0R2J-2-GP  [R402H16]  114.81 244.71 180 bottom
R1155  0R2J-2-GP  [R402H16]  114.3 233.66 90 bottom
R1156  10KR2J-3-GP  [R402H16]  147.27 18.93 270 top
R1157  20KR2F-L-GP  [R402H16]  21.08 147.05 90 top
R1158  1KR2F-3-GP  [R402H16]  79.02 80.65 90 bottom
R1159  10KR2J-L-GP  [R402H15]  96.57 94.6 0 top
R1160  -  [0R0402-PAD]  95.5 94.73 0 top
R1161  1K69R2F-2-GP  [R402H16]  93.47 95.11 0 bottom
R1162  1KR2F-3-GP  [R402H16]  92.46 95.11 0 bottom
R1165  0R0402-PAD-2-GP  [0R0402-PAD-1]  102.11 82.28 270 top
R1166  0R0402-PAD-2-GP  [0R0402-PAD-1]  102.11 81.26 270 top
R1167  10KR2J-3-GP  [R402H16]  90.04 60.31 0 top
R1168  33R2J-2-GP  [R402H16]  91.57 58.53 180 top
R1169  33R2J-2-GP  [R402H16]  92.58 58.53 180 top
R1170  33R2J-2-GP  [R402H16]  93.98 69.96 180 top
R1171  33R2J-2-GP  [R402H16]  95.12 69.96 180 top
R1183  33R2J-2-GP  [R402H16]  101.6 79.74 180 top
R1184  10KR2J-3-GP  [R402H16]  102.11 78.22 270 top
R1185  10KR2J-3-GP  [R402H16]  78.74 71.87 0 top
R1186  10KR2J-3-GP  [R402H16]  102.62 79.74 180 top
R1187  4K7R2J-2-GP  [R402H16]  96.14 93.13 270 top
R1188  1MR3F-GP  [R603H22]  95.63 97.65 180 top
R1190  10KR2J-3-GP  [R402H16]  101.85 90.15 0 top
R1191  10KR2J-3-GP  [R402H16]  100.71 90.15 0 top
R1193  10KR2J-3-GP  [R402H16]  78.74 69.96 180 top
R1197  100R2F-L1-GP-U  [R402H14]  76.2 100.19 270 bottom
R1198  100R2F-L1-GP-U  [R402H14]  71.88 101.2 90 bottom
R1199  40D2R2F-GP  [R402H16]  73.79 103.74 180 bottom
R1200  40D2R2F-GP  [R402H16]  72.64 103.74 180 bottom
R1201  120R2F-GP  [R402H16]  76.96 98.15 180 bottom
R1202  10R2F-L-GP  [R402H14]  81.28 77.83 180 bottom
R1203  47R2J-2-GP  [R402H16]  81.28 75.93 180 bottom
R1204  2K2R2J-2-GP  [R402H16]  82.3 75.93 180 bottom
R1205  4K99R2F-L-GP  [R402H16]  80.26 77.83 180 bottom
R1206  51D1R2F-GP  [R402H16]  75.31 69.83 0 top
R1207  51D1R2F-GP  [R402H16]  74.3 69.83 0 top
R1208  0R2J-2-GP  [R402H16]  116.71 234.04 180 bottom
R1209  0R2J-2-GP  [R402H16]  115.82 244.71 180 bottom
R1210  249R2F-GP  [R402H16]  89.59 85.02 0 bottom
R1211  499R2F-2-GP  [R402H16]  91.62 85.02 180 bottom
R1212  0R5J-5-GP  [R805H24]  24.49 152.64 270 bottom
R1213  0R5J-5-GP  [R805H24]  24.49 150.71 270 bottom
R1214  0R5J-5-GP  [R805H24]  24.41 143.14 270 bottom
R1215  0R5J-5-GP  [R805H24]  24.41 141.21 270 bottom
R1216  0R5J-5-GP  [R805H24]  24.41 139.28 270 bottom
R1217  0R5J-5-GP  [R805H24]  24.41 137.35 270 bottom
R1218  0R5J-5-GP  [R805H24]  24.41 135.42 270 bottom
R1219  0R5J-5-GP  [R805H24]  24.41 133.49 270 bottom
R1220  0R0603-PAD-2-GP-U  [0R0603-PAD-1-U]  86.36 8.75 0 bottom
R1221  0R2J-2-GP  [R402H16]  17.88 230.79 90 bottom
R1222  0R2J-2-GP  [R402H16]  17.91 231.86 270 bottom
R1223  -  [0R0805-PAD]  24.51 76.95 180 top
R1224  -  [0R0805-PAD]  22.48 76.95 180 top
R1225  0R2J-2-GP  [R402H16]  99.69 223.25 180 top
R1226  0R2J-2-GP  [R402H16]  20.7 29.57 0 bottom
R1227  10KR2J-3-GP  [R402H16]  19.15 33.64 180 top
R1228  10KR2J-3-GP  [R402H16]  93.65 240.47 0 bottom
R1229  0R2J-2-GP  [R402H16]  123.77 106.84 270 top
R1230  0R0603-PAD-2-GP-U  [0R0603-PAD-1-U]  70.23 8.37 0 bottom
R1231  0R0603-PAD-2-GP-U  [0R0603-PAD-1-U]  84.86 8.38 180 top
R1233  10K5R3F-GP  [R603H22]  154.56 40.7 270 top
R1234  10K5R3F-GP  [R603H22]  165.3 36.69 90 top
RJ1  RJ45-XFOR-LED-3-GP  [PT2-P0P-26B9]  20.62 11.86 180 top
RN2  SRN8K2J-4-GP  [ARES8-CN24H20]  155.44 77.62 270 top
RN5  SRN10KJ-6-GP  [ARES8-CN24-MUH20]  56.11 32.42 180 top
RN6  SRN10KJ-6-GP  [ARES8-CN24-MUH20]  45.59 31.86 180 top
RN7  SRN10KJ-6-GP  [ARES8-CN24-MUH20]  50.2 31.93 180 top
RN9  SRN2K2J-1-GP  [ARES2H16]  104.14 82.15 180 top
RR1  4K7R2J-2-GP  [R402H16]  129.16 25 270 bottom
SATAP1  DVD-CON5-26-GP  [1580C010]  6.62 100.05 90 top
SPK1  JWT-CON6-20-GP  [A1501WV0-6PS-5E]  141.52 24.55 90 top
SPR1  SPRING-39-GP-U  [SPR4330-UH71]  58.62 247.05 90 top
SRCON1  SKT-G6179-GP-U  [G6179-1000000-U]  138.04 104.21 90 top
SSUSB1  SKT-USB11-55-GP  [SKT-USB11-145165]  195.62 126.05 90 top
SSUSB2  SKT-USB11-55-GP  [SKT-USB11-145165]  195.62 105.05 90 top
TC1  ST330U2D5VDM-9GP  [CT7343H75]  99.95 231.25 0 bottom
TC2  SE47U25VM-14-GP  [SE361416H237]  162.15 217.71 180 top
TC3  SE47U25VM-14-GP  [SE361416H237]  15.49 212.2 270 top
TC4  E560U6D3VM-3-GP  [ECAP-100D6D3H375]  44.76 210.48 0 top
TC5  E820U2D5VM-7-GP  [ECAP-100D6D3H355]  156.51 208.95 0 top
TC6  E560U6D3VM-3-GP  [ECAP-100D6D3H375]  45.85 202.55 0 top
TC7  E820U2D5VM-7-GP  [ECAP-100D6D3H355]  156.57 201.05 0 top
TC8  E560U6D3VM-3-GP  [ECAP-100D6D3H375]  45.85 194.55 0 top
TC9  SE47U25VM-14-GP  [SE361416H237]  15.37 190.86 270 top
TC10  E560U6D3VM-3-GP  [ECAP-100D6D3H375]  45.85 186.67 0 top
TC11  E560U6D3VM-3-GP  [ECAP-100D6D3H375]  45.72 178.8 0 top
TC12  ST330U2D5VDM-9GP  [CT7343H75]  177.8 166.99 180 top
TC13  ST100U6D3VBM-7GP  [CT3528H79]  182.58 132.27 180 top
TC14  E820U2D5VM-7-GP  [ECAP-100D6D3H355]  157.1 111.11 0 top
TC15  ST100U6D3VBM-7GP  [CT3528H79]  184.16 110.28 0 top
TC16  E820U2D5VM-7-GP  [ECAP-100D6D3H355]  114.59 110.26 0 top
TC17  E100U16VM-22-GP  [ECAP-100D6D3H237]  171.32 90.15 0 top
TC18  E220U16VM-25-GP  [ECAP-100D6D3H473]  18.7 88.33 0 top
TC19  E100U16VM-107-GP  [ECAP-100D6D3H237]  25.32 84.01 0 top
TC20  E820U2D5VM-7-GP  [ECAP-100D6D3H355]  59.72 63.94 0 top
TC21  SE47U25VM-14-GP  [SE361416H237]  78.87 38.21 90 top
TC22  E100U16VM-107-GP  [ECAP-100D6D3H237]  114.67 25.79 0 top
TC23  ST330U2D5VDM-9GP  [CT7343H75]  141.25 114.74 0 bottom
TOUCH1  JWT-CON5-S13-GP  [A1501WV0-5P-6T-2D4]  6.62 22.05 270 top
TOUCH2  JWT-CON2-S10-GP-U  [A2001WV2-2P-U]  20.62 68.05 180 top
TP1  -  [TPAD28]  72.14 225 0 bottom
TP3  -  [TPAD28]  179.1 193.48 270 top
TP4  -  [TPAD28]  51.84 162.69 0 top
TP5  -  [TPAD28]  51.84 161.42 0 top
TP6  -  [TPAD28]  51.84 160.15 0 top
TP7  -  [TPAD28]  51.84 158.88 0 top
TP8  -  [TPAD28]  41.88 144 90 top
TP9  -  [TPAD28]  39.75 134.1 0 top
TP11  -  [TPAD28]  149.99 86.22 0 top
TP12  -  [TPAD28]  149.22 79.74 0 top
TP17  -  [TPAD28]  152.4 74.79 0 top
TP18  -  [TPAD28]  149.81 72.32 0 top
TP19  -  [TPAD28]  152.27 72.54 0 top
TP25  -  [TPAD28]  148.51 60.92 0 top
TP26  -  [TPAD28]  123.74 60.9 0 top
TP27  -  [TPAD28]  125.29 60.88 0 top
TP28  -  [TPAD28]  143.89 60.85 0 top
TP29  -  [TPAD28]  124.49 59.8 0 top
TP30  -  [TPAD28]  126.09 59.75 0 top
TP31  -  [TPAD28]  140.84 51.83 90 top
TP32  -  [TPAD28]  156.34 38.85 0 top
TP33  -  [TPAD28]  92.58 33.89 270 top
TP34  -  [TPAD28]  116.33 241.94 0 bottom
TP35  -  [TPAD28]  108.79 243.9 0 bottom
TP36  -  [TPAD28]  107.31 243.57 0 bottom
TP37  -  [TPAD28]  108.48 234.55 0 bottom
TP38  -  [TPAD28]  105.56 233.54 0 bottom
TP39  -  [TPAD28]  108.15 233.18 0 bottom
TP40  -  [TPAD28]  81.07 189.13 180 bottom
TP41  -  [TPAD28]  75.56 188.96 180 bottom
TP42  -  [TPAD28]  69.34 188.01 180 bottom
TP43  -  [TPAD28]  72.7 187.66 180 bottom
TP44  -  [TPAD28]  76.96 187.69 180 bottom
TP45  -  [TPAD28]  75.57 187.51 180 bottom
TP46  -  [TPAD28]  68.07 187.51 180 bottom
TP47  -  [TPAD28]  74.04 187.69 180 bottom
TP48  -  [TPAD28]  94.84 186.83 180 bottom
TP49  -  [TPAD28]  96.14 186.8 180 bottom
TP50  -  [TPAD28]  71.25 186.74 180 bottom
TP51  -  [TPAD28]  69.83 186.46 180 bottom
TP52  -  [TPAD28]  76.52 186.35 180 bottom
TP53  -  [TPAD28]  73.65 186.32 180 bottom
TP54  -  [TPAD28]  68.07 186.24 180 bottom
TP55  -  [TPAD28]  72.52 185.66 180 bottom
TP56  -  [TPAD28]  77.49 185.52 180 bottom
TP57  -  [TPAD28]  70.74 185.53 180 bottom
TP58  -  [TPAD28]  64.77 185.09 180 bottom
TP59  -  [TPAD28]  66.91 184.66 180 bottom
TP60  -  [TPAD28]  72.49 183.67 180 bottom
TP61  -  [TPAD28]  81.32 179.88 180 bottom
TP62  -  [TPAD28]  76.2 179.31 180 bottom
TP63  -  [TPAD28]  75.16 178.25 180 bottom
TP64  -  [TPAD28]  96.98 177.6 180 bottom
TP65  -  [TPAD28]  98.24 174.5 180 bottom
TP66  -  [TPAD28]  96.12 174.19 180 bottom
TP67  -  [TPAD28]  96.29 171.77 180 bottom
TP68  -  [TPAD28]  98.91 171.72 180 bottom
TP69  -  [TPAD28]  97.04 170.69 180 bottom
TP70  -  [TPAD28]  87.86 167.29 180 bottom
TP71  -  [TPAD28]  98.41 167.39 180 bottom
TP72  -  [TPAD28]  98.99 165.41 180 bottom
TP73  -  [TPAD28]  69.53 165.07 180 bottom
TP74  -  [TPAD28]  69.65 162.3 180 bottom
TP75  -  [TPAD28]  68.74 161.36 180 bottom
TP76  -  [TPAD28]  66.01 161.24 180 bottom
TP77  -  [TPAD28]  64.92 160.49 180 bottom
TP78  -  [TPAD28]  69.78 160.48 180 bottom
TP79  -  [TPAD28]  65.98 159.75 180 bottom
TP80  -  [TPAD28]  71.93 159.44 180 bottom
TP81  -  [TPAD28]  100.66 159.88 180 bottom
TP82  -  [TPAD28]  67.79 158.7 180 bottom
TP83  -  [TPAD28]  73.71 158.68 180 bottom
TP84  -  [TPAD28]  70.51 158.63 180 bottom
TP85  -  [TPAD28]  72.49 158.3 180 bottom
TP86  -  [TPAD28]  66.17 158.25 180 bottom
TP87  -  [TPAD28]  64.72 156.82 180 bottom
TP88  -  [TPAD28]  65.99 156.64 180 bottom
TP89  -  [TPAD28]  185.45 156.37 270 bottom
TP90  -  [TPAD28]  79.63 156.32 180 bottom
TP91  -  [TPAD28]  78.34 156.25 180 bottom
TP92  -  [TPAD28]  67.06 155.93 180 bottom
TP93  -  [TPAD28]  83.21 155.86 180 bottom
TP94  -  [TPAD28]  65.81 155.28 180 bottom
TP95  -  [TPAD28]  78.98 155.16 180 bottom
TP96  -  [TPAD28]  80.88 155.07 180 bottom
TP97  -  [TPAD28]  77.12 154.88 180 bottom
TP98  -  [TPAD28]  66.96 154.46 180 bottom
TP99  -  [TPAD28]  70.61 154.13 180 bottom
TP100  -  [TPAD28]  68.68 154.08 180 bottom
TP101  -  [TPAD28]  81.53 153.83 180 bottom
TP102  -  [TPAD28]  60.1 150.35 180 bottom
TP103  -  [TPAD28]  62.42 150.24 180 bottom
TP104  -  [TPAD28]  60.94 149.23 180 bottom
TP105  -  [TPAD28]  98.12 148.19 180 bottom
TP106  -  [TPAD28]  62.38 147.81 180 bottom
TP107  -  [TPAD28]  97.08 147.42 180 bottom
TP108  -  [TPAD28]  94.36 146.67 180 bottom
TP109  -  [TPAD28]  96.12 146.54 180 bottom
TP110  -  [TPAD28]  134.09 98.61 180 bottom
TP111  -  [TPAD28]  132.44 97.8 180 bottom
TP112  -  [TPAD28]  130.58 97.65 180 bottom
TP115  -  [TPAD28]  131.95 88.38 180 bottom
TP117  -  [TPAD28]  145.46 84.42 180 bottom
TP118  -  [TPAD28]  148.21 82.66 180 bottom
TP119  -  [TPAD28]  146.94 82.66 180 bottom
TP120  -  [TPAD28]  145.41 82.54 180 bottom
TP122  -  [TPAD28]  129.87 80.35 180 bottom
TP123  -  [TPAD28]  145.9 80.4 180 bottom
TP124  -  [TPAD28]  131.24 79.57 180 bottom
TP126  -  [TPAD28]  139.45 79.26 180 bottom
TP127  -  [TPAD28]  145.65 78.72 180 bottom
TP128  -  [TPAD28]  139.22 78.04 180 bottom
TP131  -  [TPAD28]  145.45 76.16 180 bottom
TP132  -  [TPAD28]  131.29 75.28 180 bottom
TP134  -  [TPAD28]  129.79 75.04 180 bottom
TP135  -  [TPAD28]  130.98 73.98 180 bottom
TP136  -  [TPAD28]  130.6 72.71 180 bottom
TP137  -  [TPAD28]  139.7 71.27 180 bottom
TP138  -  [TPAD28]  132.08 72.37 180 bottom
TP139  -  [TPAD28]  130.18 71.1 180 bottom
TP140  -  [TPAD28]  134.34 70.25 180 bottom
TP141  -  [TPAD28]  141.07 69.89 180 bottom
TP142  -  [TPAD28]  134.46 67.05 180 bottom
TP143  -  [TPAD28]  135.51 67.8 180 bottom
TP144  -  [TPAD28]  144.65 31.99 180 top
TP145  -  [TPAD28]  146.18 31.99 180 top
TP146  -  [TPAD28]  143.23 64.65 180 bottom
TP147  -  [TPAD28]  99.85 43.21 270 bottom
TP148  -  [TPAD28]  63.37 25.64 180 bottom
TP149  -  [TPAD28]  80.39 73.8 0 top
TP150  -  [TPAD28]  81.15 72.37 0 top
TP155  -  [TPAD28]  78.49 73.77 0 top
TP158  -  [TPAD28]  78.36 77.83 180 bottom
TP159  -  [TPAD28]  85.72 85.96 180 bottom
TP163  -  [TPAD28]  94.49 84.57 0 top
TP164  -  [TPAD28]  94.49 83.3 0 top
TP165  -  [TPAD28]  94.61 82.03 0 top
TP166  -  [TPAD28]  43.69 50.66 0 top
TP167  -  [TPAD28]  42.67 48.62 0 top
TR1  MCM1012B900FBP-GP-U  [L125100-4P-1H37]  177.65 223.91 0 top
TR2  MCM1012B900FBP-GP-U  [L125100-4P-1H37]  182.68 117.51 180 top
TR3  MCM1012B900FBP-GP-U  [L125100-4P-1H37]  182.68 115.22 180 top
TR4  FILTER-4P-120-GP  [L125100-4P-1H28]  52.58 28.3 180 top
TR5  FILTER-4P-120-GP  [L125100-4P-1H28]  40.26 28.43 180 top
TR6  FILTER-4P-120-GP  [L125100-4P-1H28]  52.58 26.15 180 top
TR7  FILTER-4P-120-GP  [L125100-4P-1H28]  39.8 25.38 180 top
TR8  MCM1012B900FBP-GP-U  [L125100-4P-1H37]  100.25 20.23 90 top
TR9  MCM1012B900FBP-GP-U  [L125100-4P-1H37]  124.51 17.94 90 top
TR10  MCM1012B900FBP-GP-U  [L125100-4P-1H37]  100.25 16.04 90 top
TR11  MCM1012B900FBP-GP-U  [L125100-4P-1H37]  126.03 14.89 90 top
TR12  MCM1012B900FBP-GP-U  [L125100-4P-1H37]  106.17 244.33 180 top
